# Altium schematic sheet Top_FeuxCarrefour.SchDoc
size A3
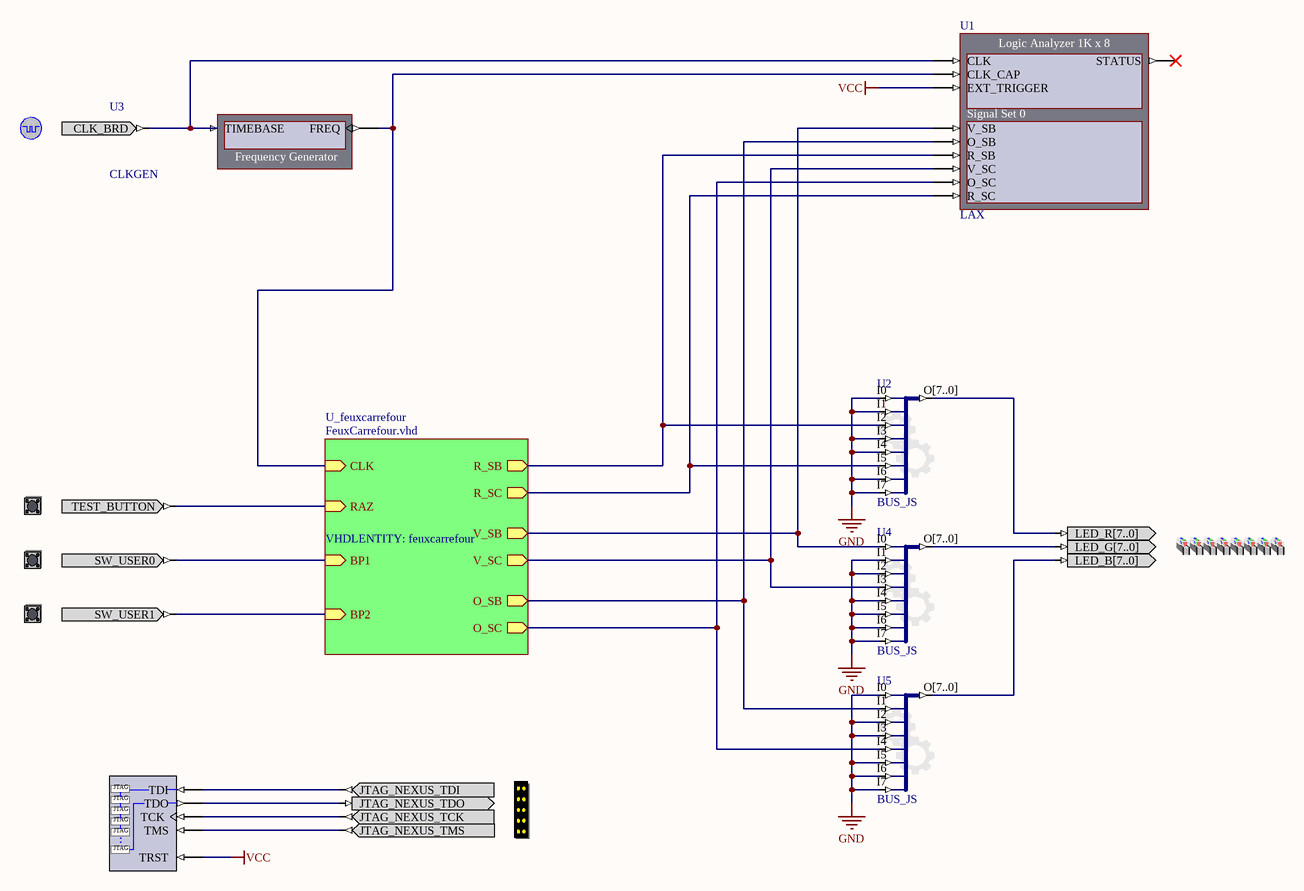
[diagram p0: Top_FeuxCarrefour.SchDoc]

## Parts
(Parts that share a designator on the sheet are numbered #1, #2 ... from top to bottom, then left to right.)
?#1  CLOCK_BOARD  (value not drawn)
?#2  TEST_BUTTON  (value not drawn)
?#3  LEDS_RGB  (value not drawn)
?#4  USER_BUTTON0  (value not drawn)
?#5  USER_BUTTON1  (value not drawn)
?#6  NEXUS_JTAG_CONNECTOR  (value not drawn)
NEXUS_JTAG_PORT  NEXUS_JTAG_PORT  (value not drawn)
U1  LAX
U2  BUS_JS
U3  CLKGEN
U4  BUS_JS
U5  BUS_JS

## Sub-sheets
U_feuxcarrefour = FeuxCarrefour.vhd: BP1 (in), BP2 (in), CLK (in), O_SB (out), O_SC (out), R_SB (out), R_SC (out), RAZ (in), V_SB (out), V_SC (out)  | VHDLENTITY: feuxcarrefour

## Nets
GND: U2.I0 U2.I1 U2.I3 U2.I4 U2.I6 U2.I7 U4.I1 U4.I2 U4.I4 U4.I5 U4.I6 U4.I7 U5.I0 U5.I2 U5.I3 U5.I5 U5.I6 U5.I7
GND_BUS[1..0]: U1.Set0_Spare[1..0]
VCC: NEXUS_JTAG_PORT.TRST U1.EXT_TRIGGER
Net?#1_CLK_BRD: ?#1.CLK_BRD U1.CLK U3.TIMEBASE
Net?#2_TEST_BUTTON: ?#2.TEST_BUTTON ; sheet U_feuxcarrefour/RAZ
Net?#4_SW_USER0: ?#4.SW_USER0 ; sheet U_feuxcarrefour/BP1
Net?#5_SW_USER1: ?#5.SW_USER1 ; sheet U_feuxcarrefour/BP2
Net?#6_JTAG_NEXUS_TCK: ?#6.JTAG_NEXUS_TCK NEXUS_JTAG_PORT.TCK
Net?#6_JTAG_NEXUS_TDI: ?#6.JTAG_NEXUS_TDI NEXUS_JTAG_PORT.TDI
Net?#6_JTAG_NEXUS_TDO: ?#6.JTAG_NEXUS_TDO NEXUS_JTAG_PORT.TDO
Net?#6_JTAG_NEXUS_TMS: ?#6.JTAG_NEXUS_TMS NEXUS_JTAG_PORT.TMS
NetU1_CLK_CAP: U1.CLK_CAP U3.FREQ ; sheet U_feuxcarrefour/CLK
NetU1_O_SB: U1.O_SB U5.I1 ; sheet U_feuxcarrefour/O_SB
NetU1_O_SC: U1.O_SC U5.I4 ; sheet U_feuxcarrefour/O_SC
NetU1_R_SB: U1.R_SB U2.I2 ; sheet U_feuxcarrefour/R_SB
NetU1_R_SC: U1.R_SC U2.I5 ; sheet U_feuxcarrefour/R_SC
NetU1_V_SB: U1.V_SB U4.I0 ; sheet U_feuxcarrefour/V_SB
NetU1_V_SC: U1.V_SC U4.I3 ; sheet U_feuxcarrefour/V_SC

Not connected (* = marked no-connect by the designer): ?#3 LED_B[7..0] LED_G[7..0] LED_R[7..0]; U1 STATUS*; U2 O[7..0]; U4 O[7..0]; U5 O[7..0]

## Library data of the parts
?#1 = CLOCK_BOARD: Global System Clock Supply; PortComponent: True
?#2 = TEST_BUTTON: Test / Reset Button; PortComponent: True
?#3 = LEDS_RGB: LEDS RGB; PortComponent: True
?#4 = USER_BUTTON0: Generic User Button; PortComponent: True
?#5 = USER_BUTTON1: Generic User Button; PortComponent: True
?#6 = NEXUS_JTAG_CONNECTOR: JTAG Port; PortComponent: True
NEXUS_JTAG_PORT = NEXUS_JTAG_PORT: Soft Nexus-Chain Connector; NEXUS_JTAG_CONNECTOR: True; FunctionalClass: JTAG
U1 = LAX: Configurable Logic Analyzer; NEXUS_CORE: Instrument; NEXUS_JTAG_DEVICE: True; NEXUS_JTAG_ORDER: 0; ConfiguratorName: LogicAnalyser; ConfigurationParameters: {}Version[1.0]{}CaptureWidth[8]{}MemorySize[1K]{}ExtAddrWidth[10]{}Set0[Signal Set 0]{}Set0_Signal0[V_SB]{}Style_Set0_Signal0[Default]{}Set0_Signal1[O_SB]{}Style_Set0_Signal1[Default]{}Set0_Signal2[R_SB]{}Style_Set0_Signal2[Default]{}Set0_Signal3[V_SC]{}Style_Set0_Signal3[Default]{}Set0_Signal4[O_SC]{}Style_Set0_Signal4[Default]{}Set0_Signal5[R_SC]{}Style_Set0_Signal5[Default]{}ConnectSpareToGND[True]{}; ChildModel1: LAX_CFG8
U2 U4 U5 = BUS_JS: Configurable Bus Joiner/Splitter; ConfiguratorName: GENERIC_BUS_JS; ConfigurationParameters: {}Version[1.1]{}SplitterJoinerType[Joiner]{}SignalCount[8]{}SignalWidth0[1]{}GapBelow0[1000000]{}ConnectionType0[Pin]{}SignalWidth1[1]{}GapBelow1[1000000]{}ConnectionType1[Pin]{}SignalWidth2[1]{}GapBelow2[1000000]{}ConnectionType2[Pin]{}SignalWidth3[1]{}GapBelow3[1000000]{}ConnectionType3[Pin]{}SignalWidth4[1]{}GapBelow4[1000000]{}ConnectionType4[Pin]{}SignalWidth5[1]{}GapBelow5[1000000]{}ConnectionType5[Pin]{}SignalWidth6[1]{}GapBelow6[1000000]{}ConnectionType6[Pin]{}SignalWidth7[1]{}GapBelow7[1000000]{}ConnectionType7[Pin]{}ShowPinNames[True]{}
U3 = CLKGEN: Frequency Generator; NEXUS_CORE: Instrument; NEXUS_JTAG_DEVICE: True; NEXUS_JTAG_ORDER: 0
